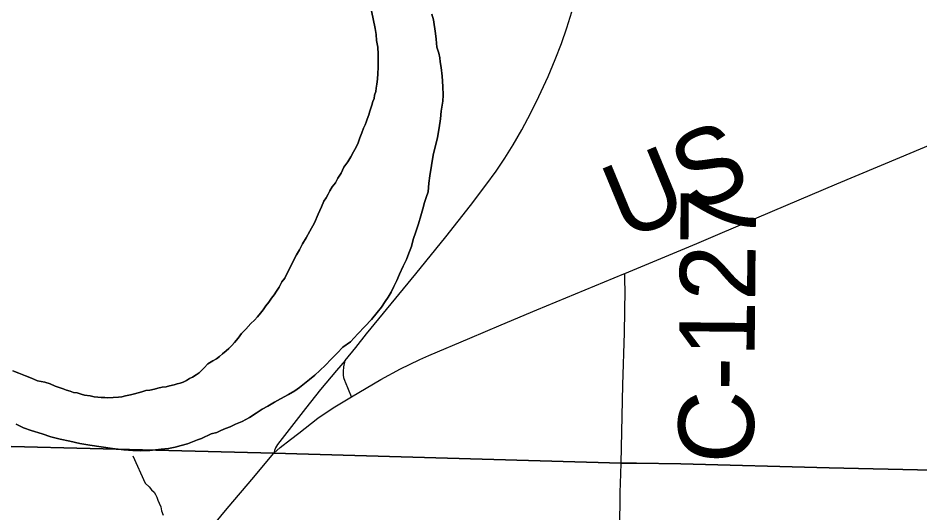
# Model space of a CAD drawing. Extents: x 0 to 64.8, y -5 to 22.
# Drawn here: x 6.296 to 6.975, y 19.777 to 20.15 of the extents above; entities that cross this region are included whole.
import ezdxf

# ---------------------------------------------------------------- set-up
doc = ezdxf.new("R2010")
doc.units = 0
for name, color, linetype in [('GM_X_Adjacent_County', 7, 'Continuous'), ('GM_X_County', 7, 'Continuous'), ('GM_X_County_Road', 7, 'Continuous'), ('GM_X_County_Road_Text', 7, 'Continuous'), ('GM_X_Major_River', 7, 'Continuous'), ('GM_X_Minor_River', 7, 'Continuous'), ('GM_X_Township', 7, 'Continuous'), ('GM_X_Township_Road', 7, 'Continuous'), ('GM_X_US_Route', 7, 'Continuous')]:
    doc.layers.add(name, color=color, linetype=linetype)

msp = doc.modelspace()

# ---------------------------------------------------------------- linework, layer by layer
at = {"layer": 'GM_X_Adjacent_County'}
for points in [[(5.389, 19.84945), (5.43252, 19.84875), (5.46984, 19.84785), (5.65344, 19.8431), (5.76533, 19.84042), (5.77168, 19.84027), (5.78773, 19.84007), (5.80115, 19.83966), (5.81576, 19.8392), (6.48839, 19.82233), (6.75027, 19.81474), (6.76179, 19.81479), (6.79501, 19.81422), (6.90684, 19.8113), (6.9845, 19.80949)], [(6.9845, 19.80949), (6.90684, 19.8113), (6.79501, 19.81422), (6.76179, 19.81479), (6.75027, 19.81474), (6.48839, 19.82233), (5.81576, 19.8392), (5.80115, 19.83966), (5.78773, 19.84007), (5.77168, 19.84027), (5.76533, 19.84042), (5.65344, 19.8431), (5.46984, 19.84785), (5.43252, 19.84875), (5.389, 19.84945)]]:
    msp.add_lwpolyline(points, dxfattribs=at)
at = {"layer": 'GM_X_County'}
for points in [[(6.9845, 19.80949), (6.90684, 19.8113), (6.79501, 19.81422), (6.76179, 19.81479), (6.75027, 19.81474), (6.48839, 19.82233), (5.81576, 19.8392), (5.80115, 19.83966), (5.78773, 19.84007), (5.77168, 19.84027), (5.76533, 19.84042), (5.65344, 19.8431), (5.46984, 19.84785), (5.43252, 19.84875), (5.389, 19.84945)], [(5.389, 19.84945), (5.43252, 19.84875), (5.46984, 19.84785), (5.65344, 19.8431), (5.76533, 19.84042), (5.77168, 19.84027), (5.78773, 19.84007), (5.80115, 19.83966), (5.81576, 19.8392), (6.48839, 19.82233), (6.75027, 19.81474), (6.76179, 19.81479), (6.79501, 19.81422), (6.90684, 19.8113), (6.9845, 19.80949)]]:
    msp.add_lwpolyline(points, dxfattribs=at)
at = {"layer": 'GM_X_County_Road'}
for points in [[(6.75284, 19.95766), (6.80726, 19.98025), (6.85244, 19.99948), (6.87417, 20.00875), (6.91252, 20.02503), (6.96007, 20.04507), (7.02717, 20.07314), (7.077, 20.09418), (7.09765, 20.10284), (7.11602, 20.11045), (7.14006, 20.12064), (7.18592, 20.13989), (7.21406, 20.15158), (7.25305, 20.16789), (7.29026, 20.18365), (7.36081, 20.21315), (7.3815, 20.22168), (7.42837, 20.24172), (7.49656, 20.27044), (7.56137, 20.29757), (7.5906, 20.30984), (7.62895, 20.32611), (7.74942, 20.37642), (7.76671, 20.38376)], [(6.54694, 19.8646), (6.56918, 19.87764), (6.58393, 19.88571), (6.59059, 19.88913), (6.59848, 19.89284), (6.60533, 19.89585), (6.63626, 19.90894), (6.65975, 19.91884), (6.68667, 19.93021), (6.75214, 19.95736), (6.75284, 19.95766)], [(6.75027, 19.81474), (6.7515, 19.8738), (6.75256, 19.91289), (6.75319, 19.94518), (6.75301, 19.95146), (6.75284, 19.95766)], [(6.73411, 18.77135), (6.73432, 18.78254), (6.73581, 18.89445), (6.73709, 18.97215), (6.73819, 19.06541), (6.74002, 19.1773), (6.741, 19.23636), (6.74204, 19.30785), (6.74276, 19.35759), (6.74349, 19.39488), (6.74441, 19.46016), (6.74594, 19.55651), (6.74712, 19.63422), (6.7481, 19.67773), (6.74866, 19.7088), (6.74907, 19.76475), (6.74951, 19.79274), (6.75002, 19.80656), (6.75027, 19.81474)]]:
    msp.add_lwpolyline(points, dxfattribs=at)
at = {"layer": 'GM_X_Major_River'}
for points in [[(6.56198, 20.15548), (6.56482, 20.14213), (6.5655, 20.13756), (6.56581, 20.133), (6.56688, 20.12804), (6.56717, 20.12271), (6.56708, 20.11702), (6.56702, 20.11284), (6.56695, 20.10828), (6.5665, 20.1041), (6.56606, 20.10031)], [(6.56606, 20.10031), (6.5665, 20.1041), (6.56695, 20.10828), (6.56702, 20.11284), (6.56708, 20.11702), (6.56717, 20.12271), (6.56688, 20.12804), (6.56581, 20.133), (6.5655, 20.13756), (6.56482, 20.14213), (6.56198, 20.15548)], [(6.32756, 19.83286), (6.33476, 19.83122), (6.34234, 19.82958), (6.34993, 19.82832), (6.35828, 19.82704), (6.36701, 19.82576), (6.37536, 19.82486), (6.3822, 19.82437), (6.38828, 19.82389), (6.39513, 19.82416), (6.40351, 19.82516), (6.40923, 19.82583), (6.41419, 19.82689), (6.41877, 19.82796), (6.42336, 19.8294), (6.42718, 19.83086), (6.43101, 19.83232), (6.43407, 19.83341), (6.44135, 19.83671), (6.44555, 19.83778), (6.44862, 19.83925), (6.45206, 19.84071), (6.45551, 19.84218), (6.45972, 19.84401), (6.4647, 19.84621), (6.47007, 19.84916), (6.47507, 19.8525), (6.47968, 19.85547), (6.4839, 19.85767), (6.48889, 19.86063), (6.4935, 19.86322), (6.49964, 19.86654), (6.50424, 19.86913), (6.5077, 19.87173), (6.51155, 19.87471), (6.5154, 19.87769), (6.51926, 19.88104), (6.52312, 19.8844), (6.52736, 19.88851), (6.53162, 19.893), (6.53625, 19.89749), (6.54051, 19.90198), (6.54628, 19.90606), (6.5517, 19.91205), (6.55711, 19.91767), (6.56214, 19.92291), (6.5664, 19.92816), (6.56951, 19.93229), (6.57224, 19.93642), (6.57457, 19.9398), (6.57692, 19.94357), (6.57888, 19.94772), (6.58124, 19.95224), (6.58321, 19.95715), (6.58597, 19.96318), (6.58833, 19.96808), (6.59031, 19.97299), (6.59229, 19.9779), (6.59351, 19.9832), (6.5955, 19.98887), (6.5975, 19.99492), (6.59911, 20.00097), (6.60072, 20.00627), (6.60194, 20.01119), (6.60314, 20.01497), (6.60473, 20.01912), (6.60521, 20.02557), (6.60606, 20.03126), (6.60858, 20.0468), (6.60941, 20.05097), (6.61061, 20.05475), (6.61183, 20.06005), (6.61309, 20.06725), (6.61396, 20.07407), (6.61443, 20.07977), (6.61526, 20.08431), (6.61569, 20.08734), (6.61614, 20.0919), (6.61586, 20.09836), (6.61522, 20.10635), (6.61456, 20.11283), (6.61387, 20.11702), (6.61353, 20.12006), (6.61283, 20.12349), (6.61138, 20.12808), (6.61071, 20.13417), (6.6104, 20.13835), (6.60969, 20.14179), (6.60936, 20.14521), (6.60866, 20.14864), (6.60758, 20.15284)], [(6.60758, 20.15284), (6.60866, 20.14864), (6.60936, 20.14521), (6.60969, 20.14179), (6.6104, 20.13835), (6.61071, 20.13417), (6.61138, 20.12808), (6.61283, 20.12349), (6.61353, 20.12006), (6.61387, 20.11702), (6.61456, 20.11283), (6.61522, 20.10635), (6.61586, 20.09836), (6.61614, 20.0919), (6.61569, 20.08734), (6.61526, 20.08431), (6.61443, 20.07977), (6.61396, 20.07407), (6.61309, 20.06725), (6.61183, 20.06005), (6.61061, 20.05475), (6.60941, 20.05097), (6.60858, 20.0468), (6.60606, 20.03126), (6.60521, 20.02557), (6.60473, 20.01912), (6.60314, 20.01497), (6.60194, 20.01119), (6.60072, 20.00627), (6.59911, 20.00097), (6.5975, 19.99492), (6.5955, 19.98887), (6.59351, 19.9832), (6.59229, 19.9779), (6.59031, 19.97299), (6.58833, 19.96808), (6.58597, 19.96318), (6.58321, 19.95715), (6.58124, 19.95224), (6.57888, 19.94772), (6.57692, 19.94357), (6.57457, 19.9398), (6.57224, 19.93642), (6.56951, 19.93229), (6.5664, 19.92816), (6.56214, 19.92291), (6.55711, 19.91767), (6.5517, 19.91205), (6.54628, 19.90606), (6.54051, 19.90198), (6.53625, 19.89749), (6.53162, 19.893), (6.52736, 19.88851), (6.52312, 19.8844), (6.51926, 19.88104), (6.5154, 19.87769), (6.51155, 19.87471), (6.5077, 19.87173), (6.50424, 19.86913), (6.49964, 19.86654), (6.4935, 19.86322), (6.48889, 19.86063), (6.4839, 19.85767), (6.47968, 19.85547), (6.47507, 19.8525), (6.47007, 19.84916), (6.4647, 19.84621), (6.45972, 19.84401), (6.45551, 19.84218), (6.45206, 19.84071), (6.44862, 19.83925), (6.44555, 19.83778), (6.44135, 19.83671), (6.43407, 19.83341), (6.43101, 19.83232), (6.42718, 19.83086), (6.42336, 19.8294), (6.41877, 19.82796), (6.41419, 19.82689), (6.40923, 19.82583), (6.40351, 19.82516), (6.39513, 19.82416), (6.38828, 19.82389), (6.3822, 19.82437), (6.37536, 19.82486), (6.36701, 19.82576), (6.35828, 19.82704), (6.34993, 19.82832), (6.34234, 19.82958), (6.33476, 19.83122), (6.32756, 19.83286)], [(6.56606, 20.10031), (6.56563, 20.09728), (6.56521, 20.09462), (6.56441, 20.09198), (6.56399, 20.08932), (6.56319, 20.08706), (6.56239, 20.08441), (6.56159, 20.08214), (6.5608, 20.07988), (6.55999, 20.07723), (6.5588, 20.07383), (6.558, 20.07156), (6.55721, 20.06967), (6.55603, 20.06703), (6.55484, 20.06363), (6.55326, 20.05986), (6.55205, 20.05608), (6.55048, 20.05268), (6.54852, 20.04929), (6.54657, 20.04552), (6.54422, 20.04176), (6.54111, 20.03763), (6.53914, 20.03311), (6.5368, 20.02934), (6.53485, 20.02595), (6.53252, 20.02295), (6.53057, 20.01994), (6.52939, 20.0173), (6.52782, 20.01467), (6.52626, 20.01203), (6.52429, 20.00788), (6.52192, 20.00222), (6.51916, 19.99581), (6.51563, 19.98941), (6.51289, 19.98451), (6.51016, 19.97999), (6.50781, 19.97547), (6.50547, 19.97171), (6.50389, 19.96831), (6.50193, 19.96455), (6.49997, 19.96078), (6.49682, 19.95399), (6.4945, 19.95137), (6.49253, 19.94722), (6.49058, 19.94421), (6.48864, 19.94158), (6.4867, 19.93895), (6.48475, 19.93595), (6.48242, 19.93332), (6.48047, 19.93031), (6.47853, 19.92769), (6.47621, 19.92506), (6.47389, 19.92244), (6.47118, 19.91983), (6.46731, 19.91571), (6.46422, 19.91234), (6.4615, 19.90896), (6.45879, 19.90559), (6.45685, 19.90334), (6.45453, 19.9011), (6.4526, 19.89923), (6.4499, 19.89699), (6.44759, 19.89513), (6.44528, 19.89327), (6.4426, 19.89179), (6.43876, 19.88957), (6.43605, 19.88658), (6.43412, 19.88471), (6.43219, 19.88284), (6.42988, 19.88136), (6.42719, 19.8795), (6.42489, 19.8784), (6.42258, 19.87691), (6.42028, 19.87581), (6.41799, 19.87509), (6.4157, 19.87437), (6.4134, 19.87364), (6.40997, 19.87294), (6.40729, 19.87222), (6.40425, 19.87189), (6.40119, 19.87118), (6.39852, 19.87047), (6.39508, 19.86976), (6.39204, 19.86943), (6.38898, 19.86834), (6.3863, 19.86763), (6.38363, 19.86691), (6.38057, 19.8662), (6.37676, 19.8655), (6.37409, 19.86478), (6.37142, 19.86445), (6.36342, 19.86382), (6.36114, 19.86423), (6.35848, 19.86428), (6.35582, 19.86432), (6.35317, 19.86475), (6.35014, 19.86555), (6.34596, 19.866), (6.34331, 19.8668), (6.34028, 19.86762), (6.33762, 19.86804)], [(6.33762, 19.86804), (6.34028, 19.86762), (6.34331, 19.8668), (6.34596, 19.866), (6.35014, 19.86555), (6.35317, 19.86475), (6.35582, 19.86432), (6.35848, 19.86428), (6.36114, 19.86423), (6.36342, 19.86382), (6.37142, 19.86445), (6.37409, 19.86478), (6.37676, 19.8655), (6.38057, 19.8662), (6.38363, 19.86691), (6.3863, 19.86763), (6.38898, 19.86834), (6.39204, 19.86943), (6.39508, 19.86976), (6.39852, 19.87047), (6.40119, 19.87118), (6.40425, 19.87189), (6.40729, 19.87222), (6.40997, 19.87294), (6.4134, 19.87364), (6.4157, 19.87437), (6.41799, 19.87509), (6.42028, 19.87581), (6.42258, 19.87691), (6.42489, 19.8784), (6.42719, 19.8795), (6.42988, 19.88136), (6.43219, 19.88284), (6.43412, 19.88471), (6.43605, 19.88658), (6.43876, 19.88957), (6.4426, 19.89179), (6.44528, 19.89327), (6.44759, 19.89513), (6.4499, 19.89699), (6.4526, 19.89923), (6.45453, 19.9011), (6.45685, 19.90334), (6.45879, 19.90559), (6.4615, 19.90896), (6.46422, 19.91234), (6.46731, 19.91571), (6.47118, 19.91983), (6.47389, 19.92244), (6.47621, 19.92506), (6.47853, 19.92769), (6.48047, 19.93031), (6.48242, 19.93332), (6.48475, 19.93595), (6.4867, 19.93895), (6.48864, 19.94158), (6.49058, 19.94421), (6.49253, 19.94722), (6.4945, 19.95137), (6.49682, 19.95399), (6.49997, 19.96078), (6.50193, 19.96455), (6.50389, 19.96831), (6.50547, 19.97171), (6.50781, 19.97547), (6.51016, 19.97999), (6.51289, 19.98451), (6.51563, 19.98941), (6.51916, 19.99581), (6.52192, 20.00222), (6.52429, 20.00788), (6.52626, 20.01203), (6.52782, 20.01467), (6.52939, 20.0173), (6.53057, 20.01994), (6.53252, 20.02295), (6.53485, 20.02595), (6.5368, 20.02934), (6.53914, 20.03311), (6.54111, 20.03763), (6.54422, 20.04176), (6.54657, 20.04552), (6.54852, 20.04929), (6.55048, 20.05268), (6.55205, 20.05608), (6.55326, 20.05986), (6.55484, 20.06363), (6.55603, 20.06703), (6.55721, 20.06967), (6.558, 20.07156), (6.5588, 20.07383), (6.55999, 20.07723), (6.5608, 20.07988), (6.56159, 20.08214), (6.56239, 20.08441), (6.56319, 20.08706), (6.56399, 20.08932), (6.56441, 20.09198), (6.56521, 20.09462), (6.56563, 20.09728), (6.56606, 20.10031)], [(6.33762, 19.86804), (6.33497, 19.86884), (6.33232, 19.86965), (6.32968, 19.87083), (6.32665, 19.87164), (6.32363, 19.87283), (6.31985, 19.87441), (6.31606, 19.87561), (6.31038, 19.87684), (6.30584, 19.87882), (6.3013, 19.88041), (6.29639, 19.88239), (6.29185, 19.88437)], [(6.29185, 19.88437), (6.29639, 19.88239), (6.3013, 19.88041), (6.30584, 19.87882), (6.31038, 19.87684), (6.31606, 19.87561), (6.31985, 19.87441), (6.32363, 19.87283), (6.32665, 19.87164), (6.32968, 19.87083), (6.33232, 19.86965), (6.33497, 19.86884), (6.33762, 19.86804)], [(6.29427, 19.84405), (6.29993, 19.84129), (6.3056, 19.8393), (6.31393, 19.83688), (6.32036, 19.8345), (6.32756, 19.83286)], [(6.32756, 19.83286), (6.32036, 19.8345), (6.31393, 19.83688), (6.3056, 19.8393), (6.29993, 19.84129), (6.29427, 19.84405)]]:
    msp.add_lwpolyline(points, dxfattribs=at)
at = {"layer": 'GM_X_Minor_River'}
msp.add_lwpolyline([(6.38218, 19.82012), (6.39162, 19.7996), (6.39459, 19.79685), (6.39642, 19.79452), (6.39828, 19.79294), (6.39936, 19.79101), (6.40044, 19.78908), (6.40114, 19.78678), (6.40221, 19.78446), (6.40327, 19.78177), (6.40395, 19.77871), (6.405, 19.77564)], dxfattribs=at)
at = {"layer": 'GM_X_Township'}
for points in [[(5.7946, 20.9), (5.79356, 20.86592), (5.7929, 20.84415), (5.76533, 19.84042), (5.77168, 19.84027), (5.78773, 19.84007), (5.80115, 19.83966), (5.81576, 19.8392), (6.48839, 19.82233), (6.75027, 19.81474), (6.76179, 19.81479), (6.79501, 19.81422), (6.90684, 19.8113), (6.9845, 19.80949)], [(6.9845, 19.80949), (6.90684, 19.8113), (6.79501, 19.81422), (6.76179, 19.81479), (6.75027, 19.81474), (6.48839, 19.82233), (5.81576, 19.8392), (5.80115, 19.83966), (5.78773, 19.84007), (5.77168, 19.84027), (5.76533, 19.84042), (5.76115, 19.7093)]]:
    msp.add_lwpolyline(points, dxfattribs=at)
at = {"layer": 'GM_X_Township_Road'}
msp.add_lwpolyline([(6.75027, 19.81474), (6.76179, 19.81479), (6.79501, 19.81422), (6.90684, 19.8113), (6.9845, 19.80949)], dxfattribs=at)
msp.add_lwpolyline([(6.75027, 19.81474), (6.76179, 19.81479), (6.79501, 19.81422), (6.90684, 19.8113), (6.9845, 19.80949)], dxfattribs=at)
at = {"layer": 'GM_X_US_Route'}
for points in [[(6.54234, 19.89218), (6.55014, 19.90191), (6.55826, 19.91209), (6.59538, 19.95723), (6.61799, 19.98534), (6.63658, 20.0087), (6.64828, 20.02405), (6.65595, 20.03464), (6.66257, 20.04446), (6.66884, 20.05452), (6.67535, 20.06588), (6.68203, 20.07856), (6.68807, 20.09085), (6.69515, 20.10611), (6.70056, 20.1187), (6.70529, 20.13091), (6.70934, 20.14271), (6.71295, 20.15464)], [(6.54234, 19.89218), (6.53573, 19.88447), (6.52362, 19.87016), (6.51246, 19.85588), (6.49133, 19.82878), (6.48971, 19.82615), (6.48893, 19.82424), (6.48839, 19.82233)], [(6.54694, 19.8646), (6.54238, 19.87569), (6.54215, 19.87624), (6.54116, 19.87912), (6.54093, 19.88136), (6.54096, 19.88371), (6.54133, 19.88734), (6.54234, 19.89218)], [(6.48839, 19.82233), (6.49336, 19.82641), (6.50114, 19.83249), (6.50741, 19.83738), (6.52175, 19.84856), (6.53327, 19.85649), (6.54694, 19.8646)], [(6.42957, 19.75164), (6.45325, 19.78047), (6.47347, 19.8041), (6.48452, 19.81743), (6.48839, 19.82233)]]:
    msp.add_lwpolyline(points, dxfattribs=at)

# ---------------------------------------------------------------- texts
at = {"layer": 'GM_X_County_Road_Text'}
for s, rotation, p in [('US', 22.49685, (6.75262, 19.98198)), ('C-127', 89.44738, (6.84989, 19.8143))]:
    msp.add_text(s, height=0.056818, rotation=rotation, dxfattribs=at).set_placement(p)

doc.saveas('drawing.dxf')
